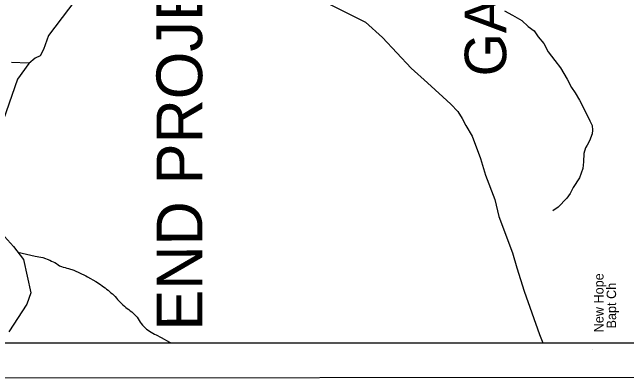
# Model space of a CAD drawing. Extents: x 1372027 to 1374286, y 553832 to 556743.
# Drawn here: x 1373235 to 1373346.9, y 554054 to 554120.7 of the extents above; entities that cross this region are included whole.
import ezdxf

# ---------------------------------------------------------------- set-up
doc = ezdxf.new("R2010")
doc.units = 0
for name, color, linetype in [('Default', 7, 'Continuous'), ('Prop Dimension', 7, 'Continuous'), ('Prop Dimension Text', 7, 'Continuous'), ('Prop Paved Shoulder', 7, 'Continuous'), ('Prop Roadway Bridge', 7, 'Continuous'), ('Sheet Clip Boundary CELL', 7, 'Continuous'), ('Sheet North Arrow Point CELL', 7, 'Continuous'), ('Sheet Sticker Preliminary CELL', 7, 'Continuous')]:
    doc.layers.add(name, color=color, linetype=linetype)

msp = doc.modelspace()

# ---------------------------------------------------------------- linework, layer by layer
at = {"layer": 'Prop Dimension'}
for points in [[(1373248.91, 554126.1), (1373241.66, 554116.47), (1373240.73, 554113.93), (1373240.11, 554112.75), (1373239.2, 554112.37), (1373238.05, 554111.41), (1373235.96, 554108.55), (1373232.91, 554099.62)], [(1373229.74, 554084.13), (1373235.24, 554078.1), (1373237.09, 554075.71), (1373238.41, 554069.66), (1373237.67, 554067.6), (1373234.41, 554062.57)]]:
    msp.add_lwpolyline(points, dxfattribs=at)
at = {"layer": 'Prop Dimension Text'}
msp.add_lwpolyline([(1373151.67, 554391.53), (1373151.67, 554060.53), (1373482.67, 554060.53), (1373482.67, 554391.53)], close=True, dxfattribs=at)
at = {"layer": 'Prop Paved Shoulder'}
msp.add_lwpolyline([(1373290.92, 554123.16), (1373299.35, 554118.91), (1373302.44, 554116.12), (1373307.64, 554110.53), (1373310.6, 554107.84), (1373313.39, 554105.33), (1373314.85, 554103.99), (1373316.13, 554102.65), (1373316.92, 554101.36), (1373317.59, 554100.13), (1373318.76, 554098.18), (1373320.27, 554094.1), (1373321.17, 554091.08), (1373322.84, 554086.61), (1373323.58, 554083.54), (1373326.1, 554076.94), (1373326.85, 554074.19), (1373328.17, 554069.95), (1373330.98, 554062.04), (1373331.61, 554060.53)], dxfattribs=at)
at = {"layer": 'Prop Roadway Bridge'}
msp.add_line((1373958.65, 554054.77), (1373123.65, 554054.02), dxfattribs=at)
at = {"layer": 'Sheet North Arrow Point CELL'}
msp.add_line((1373340.69, 554059.42), (1373340.69, 554059.42), dxfattribs=at)
at = {"layer": 'Sheet Sticker Preliminary CELL'}
for points in [[(1373324.59, 554120.99), (1373326.05, 554120.17), (1373327.75, 554119.21), (1373328.94, 554118.13), (1373330.03, 554117.31), (1373330.76, 554116.24), (1373331.79, 554115), (1373332.55, 554113.48), (1373333.78, 554111.94), (1373334.8, 554110.57), (1373336.02, 554108.53), (1373336.83, 554107.04), (1373337.48, 554106.02), (1373338.29, 554104.7), (1373339.3, 554102.7), (1373340.14, 554100.96), (1373340.55, 554100.11), (1373340.62, 554099.27), (1373340.56, 554098.6), (1373340.07, 554097.31), (1373339.67, 554096.52), (1373339.37, 554096.06), (1373339.05, 554094.98), (1373338.99, 554093.51), (1373338.88, 554092.25), (1373338.29, 554090.58), (1373337.09, 554088.8), (1373336.55, 554087.72), (1373335.98, 554086.85), (1373334.36, 554085.24), (1373333.42, 554084.55)], [(1373237.96, 554111.42), (1373234.88, 554111.56)], [(1373236.04, 554077.07), (1373239.23, 554076.34), (1373239.56, 554076.26), (1373239.9, 554076.19), (1373240.24, 554076.14), (1373240.57, 554076.06), (1373241.85, 554075.57), (1373242.17, 554075.44), (1373242.48, 554075.3), (1373242.79, 554075.14), (1373243.08, 554074.96), (1373243.37, 554074.76), (1373243.66, 554074.59), (1373243.98, 554074.46), (1373244.31, 554074.34), (1373244.64, 554074.24), (1373244.97, 554074.15), (1373245.3, 554074.07), (1373246.25, 554073.75), (1373248.45, 554072.75), (1373248.75, 554072.59), (1373250.24, 554071.73), (1373250.53, 554071.54), (1373250.81, 554071.35), (1373251.09, 554071.15), (1373251.37, 554070.94), (1373251.65, 554070.74), (1373251.92, 554070.53), (1373252.19, 554070.32), (1373252.47, 554070.11), (1373252.74, 554069.89), (1373253, 554069.67), (1373253.26, 554069.45), (1373253.51, 554069.21), (1373253.75, 554068.97), (1373253.98, 554068.71), (1373254.21, 554068.44), (1373254.44, 554068.19), (1373254.68, 554067.95), (1373254.93, 554067.71), (1373255.18, 554067.47), (1373255.44, 554067.24), (1373255.7, 554067.01), (1373255.97, 554066.8), (1373256.24, 554066.59), (1373256.52, 554066.38), (1373256.79, 554066.17), (1373257.04, 554065.94), (1373257.3, 554065.7), (1373257.54, 554065.46), (1373257.77, 554065.2), (1373257.92, 554064.89), (1373258.11, 554064.61), (1373258.31, 554064.33), (1373258.52, 554064.05), (1373258.74, 554063.79), (1373258.97, 554063.53), (1373259.21, 554063.28), (1373259.47, 554063.05), (1373259.74, 554062.85), (1373260.03, 554062.66), (1373260.33, 554062.48), (1373260.63, 554062.31), (1373260.93, 554062.15), (1373261.24, 554061.99), (1373262.15, 554061.5), (1373263.65, 554060.66), (1373263.94, 554060.53)]]:
    msp.add_lwpolyline(points, dxfattribs=at)

# ---------------------------------------------------------------- texts
at = {"layer": 'Default'}
msp.add_text('END PROJECT', height=8.3303, rotation=90.0509, dxfattribs=at).set_placement((1373269.65, 554062.79))
at = {"layer": 'Sheet Clip Boundary CELL'}
msp.add_text('GASTONIA', height=7.56, rotation=90, dxfattribs=at).set_placement((1373324.94, 554109.04))
at = {"layer": 'Sheet North Arrow Point CELL'}
for s, p in [('New Hope ', (1373342.64, 554062.46)), ('Bapt Ch', (1373344.93, 554063.16))]:
    msp.add_text(s, height=1.722, rotation=90, dxfattribs=at).set_placement(p)

doc.saveas('drawing.dxf')
